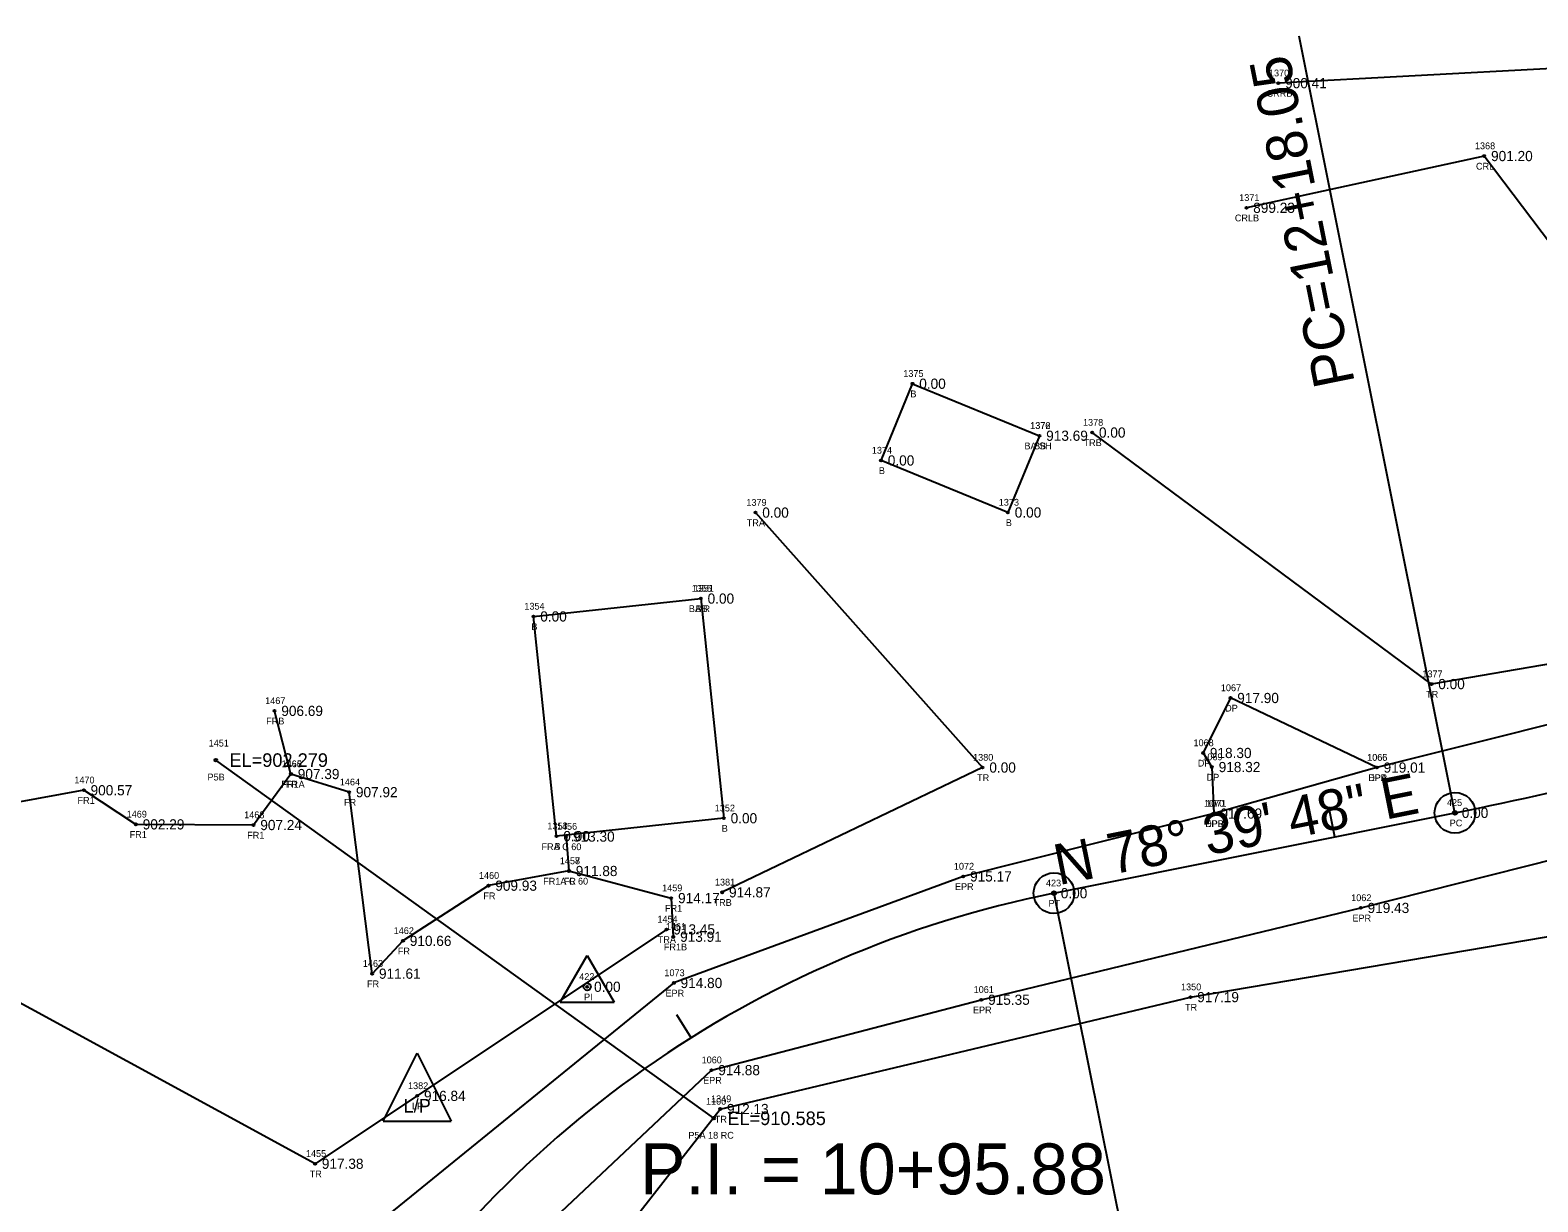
# Model space of a CAD drawing. Extents: x 1448136 to 1453623, y 1125056 to 1128842.
# Drawn here: x 1451908.2 to 1452130.2, y 1126963.9 to 1127136.4 of the extents above; entities that cross this region are included whole.
import ezdxf

# ---------------------------------------------------------------- set-up
doc = ezdxf.new("R2010")
doc.units = 0
for name, color, linetype in [('RD_EX_Bldg', 7, 'Continuous'), ('RD_EX_Bldg_txCode', 7, 'Continuous'), ('RD_EX_DR_Pipe', 7, 'Continuous'), ('RD_EX_DR_Pipe_txCode', 7, 'Continuous'), ('RD_EX_Driveway', 7, 'Continuous'), ('RD_EX_Driveway_txCode', 7, 'Continuous'), ('RD_EX_Fence_Other', 7, 'Continuous'), ('RD_EX_Fence_Other_txCode', 7, 'Continuous'), ('RD_EX_H2O', 7, 'Continuous'), ('RD_EX_H2O_txCode', 7, 'Continuous'), ('RD_EX_Road', 7, 'Continuous'), ('RD_EX_Road_txCode', 7, 'Continuous'), ('RD_EX_TX_Bldg_ELEV', 7, 'Continuous'), ('RD_EX_TX_Driveway_ELEV', 7, 'Continuous'), ('RD_EX_TX_Fence_Other_ELEV', 7, 'Continuous'), ('RD_EX_TX_H2O_ELEV', 7, 'Continuous'), ('RD_EX_TX_Road_ELEV', 7, 'Continuous'), ('RD_EX_TX_UT_ELEV', 7, 'Continuous'), ('RD_EX_TX_VEG_ELEV', 7, 'Continuous'), ('RD_EX_UT', 7, 'Continuous'), ('RD_EX_UT_txCode', 7, 'Continuous'), ('RD_EX_VEG', 7, 'Continuous'), ('RD_EX_VEG_txCode', 7, 'Continuous'), ('RD_HC_Cl', 7, 'Continuous'), ('RD_HC_Data', 7, 'Continuous'), ('RD_HC_Data_Tic', 7, 'Continuous'), ('RD_HC_Survey_ELEV', 7, 'Continuous'), ('RD_HC_txCode', 7, 'Continuous'), ('RD_SMD_Locator', 7, 'Continuous'), ('RD_TX_Pipe_ElevEX', 7, 'Continuous')]:
    doc.layers.add(name, color=color, linetype=linetype)

msp = doc.modelspace()

# ---------------------------------------------------------------- linework, layer by layer
at = {"layer": 'RD_EX_Bldg'}
for points in [[(1452056.8, 1127076.72), (1452052.17, 1127065.42), (1452033.48, 1127073.08), (1452038.11, 1127084.38), (1452056.8, 1127076.72)], [(1452006.95, 1127052.74), (1452010.34, 1127020.39), (1451985.7, 1127017.76), (1451982.31, 1127050.11), (1452006.95, 1127052.74)]]:
    msp.add_lwpolyline(points, dxfattribs=at)
at = {"layer": 'RD_EX_DR_Pipe'}
msp.add_line((1452008.86, 1126976.2), (1451935.55, 1127028.95), dxfattribs=at)
at = {"layer": 'RD_EX_Driveway'}
msp.add_lwpolyline([(1452106.48, 1127027.85), (1452084.93, 1127038.1), (1452080.9, 1127030), (1452082.2, 1127027.93), (1452082.46, 1127021.08)], dxfattribs=at)
at = {"layer": 'RD_EX_Fence_Other'}
for points in [[(1451987.13, 1127017.69), (1451987.54, 1127012.62), (1451975.69, 1127010.46), (1451963.1, 1127002.33), (1451958.56, 1126997.5), (1451955.17, 1127024.23), (1451946.61, 1127026.9), (1451944.18, 1127036.2)], [(1451946.61, 1127026.9), (1451941.09, 1127019.39), (1451923.78, 1127019.49), (1451916.1, 1127024.51), (1451898.66, 1127021.32), (1451895.26, 1127017.21)], [(1451987.54, 1127012.62), (1452002.6, 1127008.63), (1452002.9, 1127002.94)]]:
    msp.add_lwpolyline(points, dxfattribs=at)
at = {"layer": 'RD_EX_H2O'}
for points in [[(1452287.31, 1127132.93), (1452238.25, 1127137.61), (1452176.16, 1127103.01), (1452152.81, 1127094.24), (1452132.29, 1127130.82), (1452091.98, 1127128.64)], [(1452296.3, 1127118.73), (1452242.18, 1127121.92), (1452183.25, 1127088.08), (1452149.14, 1127082.38), (1452122.3, 1127117.91), (1452087.28, 1127110.29)]]:
    msp.add_lwpolyline(points, dxfattribs=at)
at = {"layer": 'RD_EX_Road'}
for points in [[(1452149.01, 1127038.49), (1452106.48, 1127027.85), (1452082.46, 1127021.08), (1452045.59, 1127011.82), (1452002.97, 1126996.13), (1451959.33, 1126960.73), (1451946.24, 1126940.07), (1451939.81, 1126935.13), (1451933.14, 1126934.05), (1451919.64, 1126943.05), (1451878.71, 1126971.14)], [(1452328.31, 1126661.73), (1452287.09, 1126689.84), (1452246.03, 1126718.01), (1452205.32, 1126746.34), (1452164.06, 1126774.06), (1452123.37, 1126802.45), (1452082.65, 1126830.42), (1452041.69, 1126858.52), (1452001.17, 1126886.81), (1451960.88, 1126914.87), (1451958.61, 1126919.72), (1451960.49, 1126923.88), (1451963.74, 1126930.05), (1451974.47, 1126951.2), (1452008.52, 1126983.3), (1452048.25, 1126993.66), (1452104.12, 1127007.18), (1452152.31, 1127019.35)]]:
    msp.add_lwpolyline(points, dxfattribs=at)
at = {"layer": 'RD_EX_UT'}
for p, q in [((1451960.19, 1126975.77), (1451965.19, 1126985.77)), ((1451965.19, 1126985.77), (1451970.19, 1126975.77)), ((1451960.19, 1126975.77), (1451970.19, 1126975.77))]:
    msp.add_line(p, q, dxfattribs=at)
at = {"layer": 'RD_EX_VEG'}
for points in [[(1452001.9, 1127004.02), (1451950.15, 1126969.51), (1451866.38, 1127015.15), (1451796.48, 1127054.28), (1451721.5, 1127099.37), (1451558.29, 1127208.56), (1451484.08, 1127271.15), (1451430.37, 1127335.12), (1451374.3, 1127375.31), (1451350.11, 1127407.35), (1451262.13, 1127463.65), (1451257.69, 1127466.25), (1451295.02, 1127593.73), (1451319.4, 1127654.86), (1451348.07, 1127713.73)], [(1452295.95, 1127072.71), (1452145.2, 1127045.38), (1452114.53, 1127040.15), (1452064.57, 1127077.19)], [(1452015, 1127065.4), (1452048.43, 1127027.86), (1452010.1, 1127009.48)], [(1452345.62, 1126685.22), (1452295.11, 1126702.27), (1452093.42, 1126839.73), (1451967.4, 1126923.31), (1452009.8, 1126977.57), (1452079.04, 1126994.05), (1452253.07, 1127023.53), (1452304.72, 1127031.75)]]:
    msp.add_lwpolyline(points, dxfattribs=at)
at = {"layer": 'RD_HC_Cl'}
msp.add_line((1452058.95, 1127009.35), (1452117.99, 1127021.19), dxfattribs=at)
for centre, radius, start, end in [((1452005.37, 1127582.96), 572.95, 281.3368, 286.9571), ((1452090.23, 1126853.3), 159.16, 101.3368, 148.8707)]:
    msp.add_arc(centre, radius, start, end, dxfattribs=at)
at = {"layer": 'RD_HC_Data'}
for p, q in [((1452117.99, 1127021.19), (1452095.07, 1127135.55)), ((1452058.95, 1127009.35), (1452081.65, 1126896.14)), ((1451986.26, 1126993.28), (1451990.23, 1127000.16)), ((1451990.23, 1127000.16), (1451994.2, 1126993.28)), ((1451986.26, 1126993.28), (1451994.2, 1126993.28))]:
    msp.add_line(p, q, dxfattribs=at)
for centre, radius in [((1452117.99, 1127021.19), 3), ((1452117.99, 1127021.19), 0.282), ((1452058.95, 1127009.35), 3), ((1452058.95, 1127009.35), 0.282), ((1451990.23, 1126995.57), 0.529)]:
    msp.add_circle(centre, radius, dxfattribs=at)
at = {"layer": 'RD_HC_Data_Tic'}
for p, q in [((1452100.3, 1127017.64), (1452099.51, 1127021.56)), ((1452005.53, 1126988.04), (1452003.4, 1126991.43))]:
    msp.add_line(p, q, dxfattribs=at)
at = {"layer": 'RD_SMD_Locator'}
for centre, radius in [((1452091.98, 1127128.64), 0.15), ((1452122.3, 1127117.91), 0.15), ((1452087.28, 1127110.29), 0.15), ((1452038.11, 1127084.38), 0.15), ((1452056.8, 1127076.72), 0.15), ((1452056.8, 1127076.72), 0.15), ((1452064.57, 1127077.19), 0.15), ((1452033.48, 1127073.08), 0.15), ((1452015, 1127065.4), 0.15), ((1452052.17, 1127065.42), 0.15), ((1452006.95, 1127052.74), 0.15), ((1452006.95, 1127052.74), 0.15), ((1451982.31, 1127050.11), 0.15), ((1452114.53, 1127040.15), 0.15), ((1452084.93, 1127038.1), 0.15), ((1451944.18, 1127036.2), 0.15), ((1451935.55, 1127028.95), 0.2), ((1452080.9, 1127030), 0.15), ((1451946.61, 1127026.9), 0.15), ((1451946.61, 1127026.9), 0.15), ((1452048.43, 1127027.86), 0.15), ((1452082.2, 1127027.93), 0.15), ((1452106.48, 1127027.85), 0.15), ((1452106.48, 1127027.85), 0.15), ((1451916.1, 1127024.51), 0.15), ((1451955.17, 1127024.23), 0.15), ((1452010.34, 1127020.39), 0.15), ((1452082.46, 1127021.08), 0.15), ((1452082.46, 1127021.08), 0.15), ((1452117.99, 1127021.19), 0.15), ((1451923.78, 1127019.49), 0.15), ((1451941.09, 1127019.39), 0.15), ((1451985.7, 1127017.76), 0.15), ((1451987.13, 1127017.69), 0.15), ((1451987.54, 1127012.62), 0.15), ((1451987.54, 1127012.62), 0.15), ((1452045.59, 1127011.82), 0.15), ((1451975.69, 1127010.46), 0.15), ((1452002.6, 1127008.63), 0.15), ((1452010.1, 1127009.48), 0.15), ((1452058.95, 1127009.35), 0.15), ((1452104.12, 1127007.18), 0.15), ((1451963.1, 1127002.33), 0.15), ((1452001.9, 1127004.02), 0.15), ((1452002.9, 1127002.94), 0.15), ((1451958.56, 1126997.5), 0.15), ((1451990.23, 1126995.57), 0.15), ((1452002.97, 1126996.13), 0.15), ((1452048.25, 1126993.66), 0.15), ((1452079.04, 1126994.05), 0.15), ((1452008.52, 1126983.3), 0.15), ((1451965.19, 1126979.5), 0.15), ((1452009.8, 1126977.57), 0.15), ((1452008.86, 1126976.2), 0.2), ((1451950.15, 1126969.51), 0.15)]:
    msp.add_circle(centre, radius, dxfattribs=at)

# ---------------------------------------------------------------- texts
at = {"layer": 'RD_EX_Bldg_txCode'}
for s, p in [('1375', (1452036.76, 1127085.38)), ('B', (1452037.8, 1127082.38)), ('1376', (1452055.43, 1127077.72)), ('1372', (1452055.46, 1127077.72)), ('BA SH', (1452054.6, 1127074.72)), ('BB', (1452056.02, 1127074.72)), ('1374', (1452032.13, 1127074.08)), ('B', (1452033.17, 1127071.08)), ('1373', (1452050.82, 1127066.42)), ('B', (1452051.86, 1127063.42)), ('1355', (1452005.6, 1127053.74)), ('1351', (1452005.89, 1127053.74)), ('1354', (1451980.97, 1127051.11)), ('BA R', (1452005.19, 1127050.74)), ('BB', (1452006.17, 1127050.74)), ('B', (1451982, 1127048.11)), ('1352', (1452009, 1127021.39)), ('1353', (1451984.36, 1127018.76)), ('B', (1452010.03, 1127018.39)), ('B', (1451985.4, 1127015.76))]:
    msp.add_text(s, height=1, dxfattribs=at).set_placement(p)
at = {"layer": 'RD_EX_DR_Pipe_txCode'}
for s, p in [('1451', (1451934.49, 1127030.95)), ('P5B', (1451934.32, 1127025.95)), ('1100', (1452007.72, 1126978.2)), ('P5A 18 RC', (1452005.12, 1126973.2))]:
    msp.add_text(s, height=1, dxfattribs=at).set_placement(p)
at = {"layer": 'RD_EX_Driveway_txCode'}
for s, p in [('1067', (1452083.52, 1127039.1)), ('DP', (1452084.15, 1127036.1)), ('1068', (1452079.49, 1127031)), ('DP', (1452080.12, 1127028)), ('1069', (1452080.79, 1127028.93)), ('1066', (1452105.05, 1127028.85)), ('DP', (1452081.42, 1127025.93)), ('DPA', (1452105.22, 1127025.85)), ('1070', (1452081.04, 1127022.08)), ('DPB', (1452081.21, 1127019.08))]:
    msp.add_text(s, height=1, dxfattribs=at).set_placement(p)
at = {"layer": 'RD_EX_Fence_Other_txCode'}
for s, p in [('1467', (1451942.81, 1127037.2)), ('FRB', (1451942.96, 1127034.2)), ('1466', (1451945.22, 1127027.9)), ('1465', (1451945.24, 1127027.9)), ('1470', (1451914.71, 1127025.51)), ('FR1A', (1451945.2, 1127024.9)), ('FR', (1451945.85, 1127024.9)), ('1464', (1451953.8, 1127025.23)), ('FR1', (1451915.18, 1127022.51)), ('FR', (1451954.42, 1127022.23)), ('1469', (1451922.41, 1127020.49)), ('1468', (1451939.72, 1127020.39)), ('FR1', (1451922.86, 1127017.49)), ('FR1', (1451940.16, 1127017.39)), ('1456', (1451985.76, 1127018.69)), ('FRA C 60', (1451983.49, 1127015.69)), ('1458', (1451986.19, 1127013.62)), ('1457', (1451986.19, 1127013.62)), ('1460', (1451974.28, 1127011.46)), ('FR1A C 60', (1451983.74, 1127010.62)), ('FR', (1451986.78, 1127010.62)), ('FR', (1451974.93, 1127008.46)), ('1459', (1452001.25, 1127009.63)), ('FR1', (1452001.68, 1127006.63)), ('1462', (1451961.73, 1127003.33)), ('1461', (1452001.81, 1127003.94)), ('FR', (1451962.34, 1127000.33)), ('FR1B', (1452001.51, 1127000.94)), ('1463', (1451957.19, 1126998.5)), ('FR', (1451957.8, 1126995.5))]:
    msp.add_text(s, height=1, dxfattribs=at).set_placement(p)
at = {"layer": 'RD_EX_H2O_txCode'}
for s, p in [('1370', (1452090.6, 1127129.64)), ('CRRB', (1452090.26, 1127126.64)), ('1368', (1452120.93, 1127118.91)), ('CRL', (1452121.08, 1127115.91)), ('1371', (1452086.22, 1127111.29)), ('CRLB', (1452085.58, 1127108.29))]:
    msp.add_text(s, height=1, dxfattribs=at).set_placement(p)
at = {"layer": 'RD_EX_Road_txCode'}
for s, p in [('1065', (1452105.07, 1127028.85)), ('EPR', (1452105.26, 1127025.85)), ('1071', (1452081.36, 1127022.08)), ('EPR', (1452081.23, 1127019.08)), ('1072', (1452044.21, 1127012.82)), ('EPR', (1452044.37, 1127009.82)), ('1062', (1452102.71, 1127008.18)), ('EPR', (1452102.89, 1127005.18)), ('1073', (1452001.59, 1126997.13)), ('1061', (1452047.12, 1126994.66)), ('EPR', (1452001.75, 1126994.13)), ('EPR', (1452047.02, 1126991.66)), ('1060', (1452007.07, 1126984.3)), ('EPR', (1452007.29, 1126981.3))]:
    msp.add_text(s, height=1, dxfattribs=at).set_placement(p)
at = {"layer": 'RD_EX_TX_Bldg_ELEV'}
for s, p in [('0.00', (1452039.11, 1127083.63)), ('913.69', (1452057.8, 1127075.97)), ('913.69', (1452057.8, 1127075.97)), ('0.00', (1452034.48, 1127072.33)), ('0.00', (1452053.17, 1127064.67)), ('0.00', (1452007.95, 1127051.99)), ('0.00', (1452007.95, 1127051.99)), ('0.00', (1451983.31, 1127049.36)), ('0.00', (1452011.34, 1127019.64)), ('0.00', (1451986.7, 1127017.01))]:
    msp.add_text(s, height=1.5, dxfattribs=at).set_placement(p)
at = {"layer": 'RD_EX_TX_Driveway_ELEV'}
for s, p in [('917.90', (1452085.93, 1127037.35)), ('918.30', (1452081.9, 1127029.25)), ('918.32', (1452083.2, 1127027.18)), ('919.01', (1452107.48, 1127027.1)), ('917.69', (1452083.46, 1127020.33))]:
    msp.add_text(s, height=1.5, dxfattribs=at).set_placement(p)
at = {"layer": 'RD_EX_TX_Fence_Other_ELEV'}
for s, p in [('906.69', (1451945.18, 1127035.45)), ('907.39', (1451947.61, 1127026.15)), ('907.39', (1451947.61, 1127026.15)), ('900.57', (1451917.1, 1127023.76)), ('907.92', (1451956.17, 1127023.48)), ('902.29', (1451924.78, 1127018.74)), ('907.24', (1451942.09, 1127018.64)), ('913.30', (1451988.13, 1127016.94)), ('911.88', (1451988.54, 1127011.87)), ('911.88', (1451988.54, 1127011.87)), ('909.93', (1451976.69, 1127009.71)), ('914.17', (1452003.6, 1127007.88)), ('910.66', (1451964.1, 1127001.58)), ('913.91', (1452003.9, 1127002.19)), ('911.61', (1451959.56, 1126996.75))]:
    msp.add_text(s, height=1.5, dxfattribs=at).set_placement(p)
at = {"layer": 'RD_EX_TX_H2O_ELEV'}
for s, p in [('900.41', (1452092.98, 1127127.89)), ('901.20', (1452123.3, 1127117.16)), ('899.23', (1452088.28, 1127109.54))]:
    msp.add_text(s, height=1.5, dxfattribs=at).set_placement(p)
at = {"layer": 'RD_EX_TX_Road_ELEV'}
for s, p in [('919.01', (1452107.48, 1127027.1)), ('917.69', (1452083.46, 1127020.33)), ('915.17', (1452046.59, 1127011.07)), ('919.43', (1452105.12, 1127006.43)), ('914.80', (1452003.97, 1126995.38)), ('915.35', (1452049.25, 1126992.91)), ('914.88', (1452009.52, 1126982.55))]:
    msp.add_text(s, height=1.5, dxfattribs=at).set_placement(p)
at = {"layer": 'RD_EX_TX_UT_ELEV'}
msp.add_text('916.84', height=1.5, dxfattribs=at).set_placement((1451966.19, 1126978.75))
at = {"layer": 'RD_EX_TX_VEG_ELEV'}
for s, p in [('0.00', (1452065.57, 1127076.44)), ('0.00', (1452016, 1127064.65)), ('0.00', (1452115.53, 1127039.4)), ('0.00', (1452049.43, 1127027.11)), ('914.87', (1452011.1, 1127008.73)), ('913.45', (1452002.9, 1127003.27)), ('917.19', (1452080.04, 1126993.3)), ('912.13', (1452010.8, 1126976.82)), ('917.38', (1451951.15, 1126968.76))]:
    msp.add_text(s, height=1.5, dxfattribs=at).set_placement(p)
at = {"layer": 'RD_EX_UT'}
msp.add_text('L/P', height=2, dxfattribs=at).set_placement((1451963.18, 1126977.05))
at = {"layer": 'RD_EX_UT_txCode'}
for s, p in [('1382', (1451963.84, 1126980.5)), ('LP', (1451964.43, 1126977.5))]:
    msp.add_text(s, height=1, dxfattribs=at).set_placement(p)
at = {"layer": 'RD_EX_VEG_txCode'}
for s, p in [('1378', (1452063.22, 1127078.19)), ('TRB', (1452063.3, 1127075.19)), ('1379', (1452013.66, 1127066.4)), ('TRA', (1452013.72, 1127063.4)), ('1377', (1452113.19, 1127041.15)), ('TR', (1452113.74, 1127038.15)), ('1380', (1452047.04, 1127028.86)), ('TR', (1452047.63, 1127025.86)), ('1381', (1452009.03, 1127010.48)), ('TRB', (1452008.83, 1127007.48)), ('1454', (1452000.56, 1127005.02)), ('TRA', (1452000.62, 1127002.02)), ('1350', (1452077.65, 1126995.05)), ('TR', (1452078.24, 1126992.05)), ('1349', (1452008.46, 1126978.57)), ('TR', (1452009.01, 1126975.57)), ('1455', (1451948.81, 1126970.51)), ('TR', (1451949.36, 1126967.51))]:
    msp.add_text(s, height=1, dxfattribs=at).set_placement(p)
at = {"layer": 'RD_HC_Data'}
for s, rotation, p in [('PC=12+18.05', 101.3368, (1452103.26, 1127084.53)), ('N 78%%d 39\' 48" E', 11.3368, (1452059.62, 1127010.51))]:
    msp.add_text(s, height=6, rotation=rotation, dxfattribs=at).set_placement(p)
msp.add_text('P.I. = 10+95.88', height=7.5, dxfattribs=at).set_placement((1451998, 1126965))
at = {"layer": 'RD_HC_Survey_ELEV'}
for p in [(1452118.99, 1127020.44), (1452059.95, 1127008.6), (1451991.23, 1126994.82)]:
    msp.add_text('0.00', height=1.5, dxfattribs=at).set_placement(p)
at = {"layer": 'RD_HC_txCode'}
for s, p in [('425', (1452116.81, 1127022.19)), ('PC', (1452117.21, 1127019.19)), ('423', (1452057.77, 1127010.35)), ('PT', (1452058.15, 1127007.35)), ('422', (1451989.05, 1126996.57)), ('PI', (1451989.76, 1126993.57))]:
    msp.add_text(s, height=1, dxfattribs=at).set_placement(p)
at = {"layer": 'RD_TX_Pipe_ElevEX'}
for s, p in [('EL=902.279', (1451937.55, 1127027.95)), ('EL=910.585', (1452010.86, 1126975.2))]:
    msp.add_text(s, height=2, dxfattribs=at).set_placement(p)

doc.saveas('drawing.dxf')
